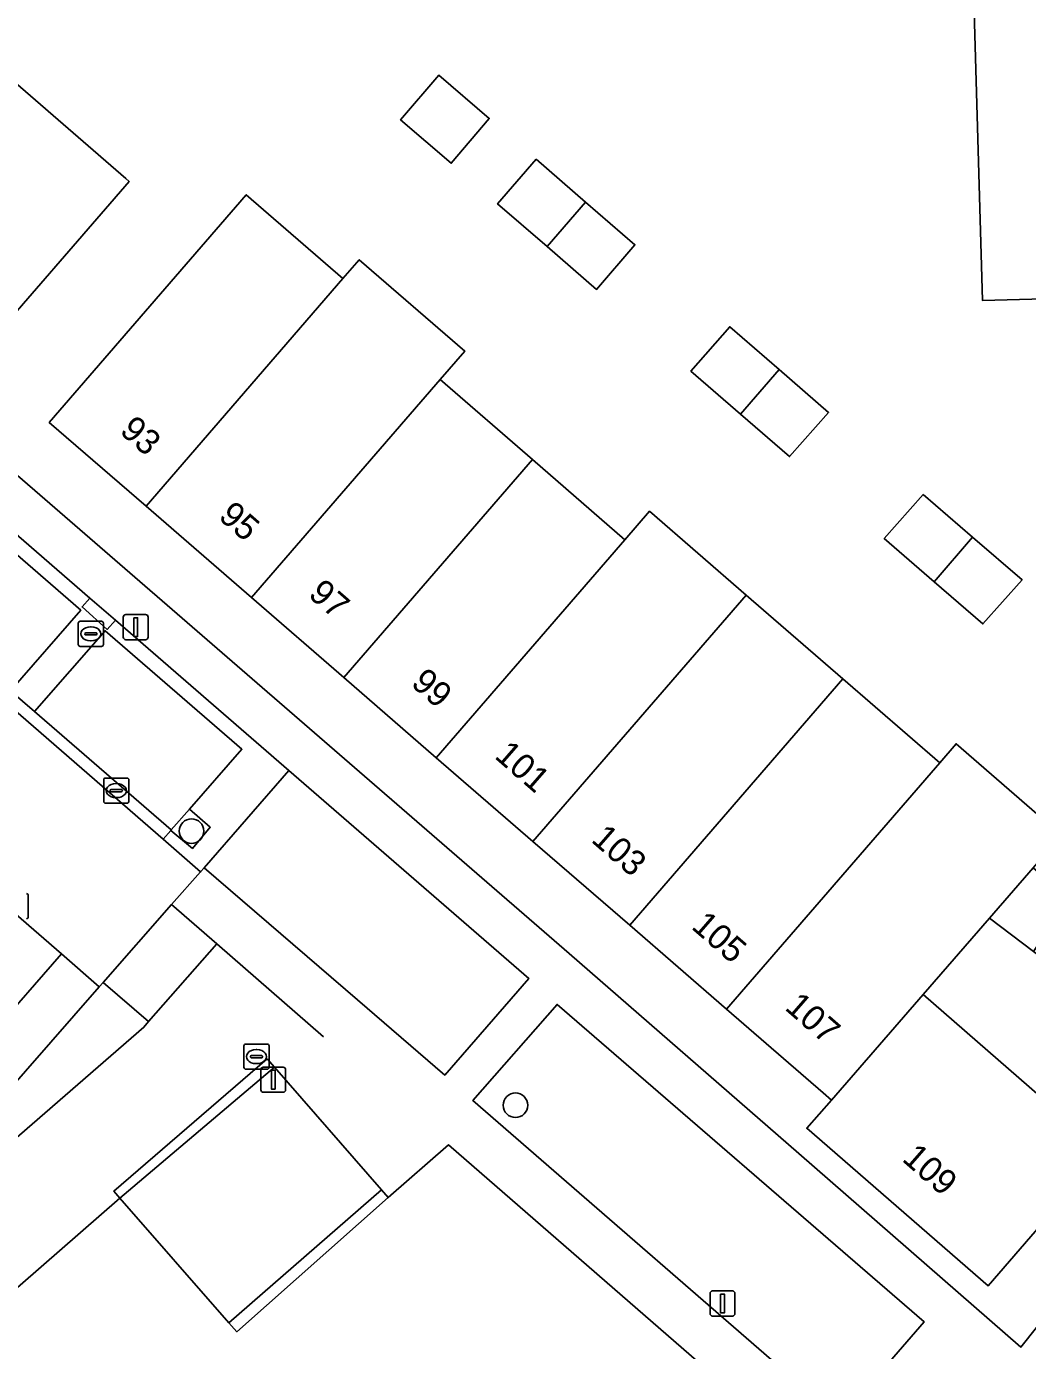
# Model space of a CAD drawing. Extents: x 161881 to 162523, y 381678 to 382381.
# Drawn here: x 162037.1 to 162077, y 382137.3 to 382190.1 of the extents above; entities that cross this region are included whole.
import ezdxf

# ---------------------------------------------------------------- set-up
doc = ezdxf.new("R2010")
doc.units = 0
for name, color, linetype in [('IMGEO_Boom', 7, 'Continuous'), ('IMGEO_Erf', 7, 'Continuous'), ('IMGEO_Groenvoorziening', 7, 'Continuous'), ('IMGEO_Kolk', 7, 'Continuous'), ('IMGEO_Lichtmast', 7, 'Continuous'), ('IMGEO_Muur', 7, 'Continuous'), ('IMGEO_Pand', 7, 'Continuous'), ('IMGEO_Pand_nummerreeks', 7, 'Continuous'), ('IMGEO_Parkeervlak_open', 7, 'Continuous'), ('IMGEO_Rijbaan_lokaal_open', 7, 'Continuous'), ('IMGEO_Rioolput', 7, 'Continuous'), ('IMGEO_Voetpad_op_trap', 7, 'Continuous'), ('IMGEO_Voetpad_open', 7, 'Continuous')]:
    doc.layers.add(name, color=color, linetype=linetype)

msp = doc.modelspace()

# ---------------------------------------------------------------- linework, layer by layer
at = {"layer": 'IMGEO_Boom'}
for centre in [(162043.641, 382158.015), (162056.555, 382147.095)]:
    msp.add_circle(centre, 0.489, dxfattribs=at)
at = {"layer": 'IMGEO_Erf'}
for points in [[(162018.121, 382203.859), (162041.023, 382184.008), (162041.152, 382183.891), (162035.04, 382176.852)], [(162081.552, 382179.326), (162075.168, 382179.155), (162074.741, 382193.897)], [(162078.978, 382144.027), (162075.391, 382139.899), (162068.168, 382146.176), (162069.146, 382147.302), (162068.814, 382147.589), (162064.963, 382150.924), (162061.108, 382154.263), (162057.252, 382157.602), (162053.397, 382160.94), (162049.714, 382164.13), (162046.032, 382167.319), (162041.828, 382170.959), (162037.971, 382174.299), (162045.823, 382183.364), (162049.678, 382180.025), (162050.33, 382180.778), (162054.534, 382177.137), (162053.552, 382176.003), (162057.235, 382172.814), (162060.917, 382169.624), (162061.899, 382170.758), (162065.755, 382167.418), (162069.61, 382164.079), (162073.466, 382160.739), (162074.121, 382161.495), (162077.841, 382158.272)], [(162034.901, 382173.742), (162058.69, 382153.142), (162067.845, 382145.177), (162076.705, 382137.459), (162080.965, 382142.814)]]:
    msp.add_lwpolyline(points, dxfattribs=at)
for points in [[(162055.51, 382186.41), (162053.994, 382184.622), (162051.976, 382186.353), (162053.505, 382188.131)], [(162057.377, 382184.78), (162059.348, 382183.077), (162061.318, 382181.373), (162059.787, 382179.597), (162057.814, 382181.302), (162055.845, 382183.003)], [(162067.068, 382176.399), (162069.039, 382174.69), (162067.483, 382172.937), (162065.531, 382174.627), (162063.551, 382176.342), (162065.097, 382178.108)], [(162072.803, 382171.429), (162074.775, 382169.729), (162076.747, 382168.029), (162075.189, 382166.27), (162073.242, 382167.951), (162071.254, 382169.668)], [(162077.199, 382153.219), (162075.448, 382154.554), (162072.802, 382151.509), (162080.025, 382145.232), (162078.978, 382144.027), (162079.761, 382143.345), (162080.668, 382142.557), (162080.678, 382142.57), (162080.908, 382142.859), (162082.372, 382144.704), (162084.632, 382147.554), (162084.682, 382147.616), (162084.141, 382148.045), (162084.083, 382147.972)]]:
    msp.add_lwpolyline(points, close=True, dxfattribs=at)
at = {"layer": 'IMGEO_Groenvoorziening'}
for points in [[(162047.527, 382160.427), (162044.151, 382156.557), (162050.254, 382151.288), (162053.738, 382148.295), (162057.087, 382152.15)], [(162043.557, 382158.895), (162042.829, 382158.065), (162042.811, 382158.044), (162043.675, 382157.326), (162044.388, 382158.167)], [(162041.933, 382150.436), (162040.113, 382151.987), (162039.963, 382151.816), (162031.132, 382141.739), (162031.515, 382141.331), (162041.747, 382150.205)], [(162058.213, 382151.114), (162054.859, 382147.282), (162069.486, 382134.586), (162072.851, 382138.463)], [(162051.211, 382143.73), (162046.944, 382148.616), (162040.79, 382143.399), (162045.133, 382138.43)], [(162065.711, 382135.244), (162053.879, 382145.512), (162051.478, 382143.425), (162045.443, 382138.075), (162045.133, 382138.43), (162040.79, 382143.399), (162034.496, 382137.927), (162055.435, 382113.796), (162063.942, 382121.182), (162066.058, 382123), (162059.846, 382130.148)]]:
    msp.add_lwpolyline(points, close=True, dxfattribs=at)
at = {"layer": 'IMGEO_Kolk'}
for p, q in [((162040.142, 382159.202), (162040.142, 382160.054)), ((162040.217, 382160.128), (162041.069, 382160.128)), ((162040.444, 382159.671), (162040.842, 382159.671)), ((162040.63, 382159.908), (162040.655, 382159.908)), ((162041.143, 382160.054), (162041.143, 382159.202)), ((162041.069, 382159.128), (162040.217, 382159.128)), ((162040.401, 382159.622), (162040.401, 382159.634)), ((162040.839, 382159.585), (162040.441, 382159.585)), ((162040.653, 382159.348), (162040.628, 382159.348)), ((162040.885, 382159.634), (162040.885, 382159.622)), ((162037.136, 382155.45), (162037.136, 382154.598)), ((162045.731, 382148.606), (162045.731, 382149.458)), ((162045.806, 382149.532), (162046.658, 382149.532)), ((162046.219, 382149.312), (162046.244, 382149.312)), ((162046.732, 382149.458), (162046.732, 382148.606)), ((162045.99, 382149.026), (162045.99, 382149.038)), ((162046.428, 382148.989), (162046.03, 382148.989)), ((162046.033, 382149.075), (162046.431, 382149.075)), ((162046.242, 382148.752), (162046.217, 382148.752)), ((162046.474, 382149.038), (162046.474, 382149.026)), ((162046.658, 382148.532), (162045.806, 382148.532))]:
    msp.add_line(p, q, dxfattribs=at)
for points in [[(162040.142, 382159.202), (162040.142, 382160.054)], [(162040.217, 382160.128), (162041.069, 382160.128)], [(162041.143, 382160.054), (162041.143, 382159.202)], [(162041.069, 382159.128), (162040.217, 382159.128)], [(162037.136, 382155.45), (162037.136, 382154.598)], [(162045.731, 382148.606), (162045.731, 382149.458)], [(162045.806, 382149.532), (162046.658, 382149.532)], [(162046.732, 382149.458), (162046.732, 382148.606)], [(162046.658, 382148.532), (162045.806, 382148.532)]]:
    msp.add_lwpolyline(points, dxfattribs=at)
for centre, radius, start, end in [((162040.219, 382160.052), 0.0765, 91.552, 178.448), ((162040.219, 382160.052), 0.0765, 91.552, 178.448), ((162040.441, 382159.631), 0.0403, 85.8775, 175.7526), ((162040.846, 382159.633), 0.0386, 1.7309, 96.639), ((162041.067, 382160.052), 0.0765, 1.552, 88.448), ((162041.067, 382160.052), 0.0765, 1.552, 88.448), ((162040.219, 382159.204), 0.0765, 181.552, 268.448), ((162040.219, 382159.204), 0.0765, 181.552, 268.448), ((162040.438, 382159.621), 0.0366, 178.938, 274.7102), ((162040.842, 382159.628), 0.043, 264.8664, 352.4533), ((162041.067, 382159.204), 0.0765, 271.552, 358.448), ((162041.067, 382159.204), 0.0765, 271.552, 358.448), ((162037.06, 382155.448), 0.0765, 1.552, 88.448), ((162037.06, 382155.448), 0.0765, 1.552, 88.448), ((162037.06, 382154.6), 0.0765, 271.552, 358.448), ((162037.06, 382154.6), 0.0765, 271.552, 358.448), ((162045.808, 382149.456), 0.0765, 91.552, 178.448), ((162045.808, 382149.456), 0.0765, 91.552, 178.448), ((162046.656, 382149.456), 0.0765, 1.552, 88.448), ((162046.656, 382149.456), 0.0765, 1.552, 88.448), ((162045.808, 382148.608), 0.0765, 181.552, 268.448), ((162045.808, 382148.608), 0.0765, 181.552, 268.448), ((162046.03, 382149.035), 0.0403, 85.8775, 175.7526), ((162046.027, 382149.025), 0.0366, 178.938, 274.7102), ((162046.431, 382149.032), 0.043, 264.8664, 352.4533), ((162046.435, 382149.037), 0.0386, 1.7309, 96.639), ((162046.656, 382148.608), 0.0765, 271.552, 358.448), ((162046.656, 382148.608), 0.0765, 271.552, 358.448)]:
    msp.add_arc(centre, radius, start, end, dxfattribs=at)
for centre, major_axis, ratio, start_param, end_param in [((162040.629, 382159.628), (-0.387, 0.002), 0.722429, 4.712389, 7.853982), ((162040.654, 382159.628), (-0.39, 0.002), 0.717154, 1.570796, 4.712389), ((162046.218, 382149.032), (-0.387, 0.002), 0.722429, 4.712389, 7.853982), ((162046.243, 382149.032), (-0.39, 0.002), 0.717154, 1.570796, 4.712389)]:
    msp.add_ellipse(centre, major_axis=major_axis, ratio=ratio, start_param=start_param, end_param=end_param, dxfattribs=at)
at = {"layer": 'IMGEO_Lichtmast'}
for p, q in [((162040.922, 382165.741), (162040.922, 382166.541)), ((162040.922, 382166.541), (162040.922, 382165.741)), ((162041.022, 382166.641), (162041.812, 382166.641)), ((162041.812, 382166.641), (162041.022, 382166.641)), ((162041.912, 382166.541), (162041.912, 382165.741)), ((162041.912, 382165.741), (162041.912, 382166.541)), ((162041.812, 382165.641), (162041.022, 382165.641)), ((162041.022, 382165.641), (162041.812, 382165.641)), ((162046.504, 382148.611), (162047.294, 382148.611)), ((162047.294, 382148.611), (162046.504, 382148.611)), ((162046.404, 382147.711), (162046.404, 382148.511)), ((162046.404, 382148.511), (162046.404, 382147.711)), ((162047.394, 382148.511), (162047.394, 382147.711)), ((162047.394, 382147.711), (162047.394, 382148.511)), ((162047.294, 382147.611), (162046.504, 382147.611)), ((162046.504, 382147.611), (162047.294, 382147.611)), ((162064.414, 382139.697), (162065.204, 382139.697)), ((162065.204, 382139.697), (162064.414, 382139.697)), ((162064.314, 382138.797), (162064.314, 382139.597)), ((162064.314, 382139.597), (162064.314, 382138.797)), ((162065.304, 382139.597), (162065.304, 382138.797)), ((162065.304, 382138.797), (162065.304, 382139.597)), ((162065.204, 382138.697), (162064.414, 382138.697)), ((162064.414, 382138.697), (162065.204, 382138.697))]:
    msp.add_line(p, q, dxfattribs=at)
for points in [[(162041.342, 382166.516), (162041.492, 382166.516), (162041.492, 382165.766), (162041.342, 382165.766), (162041.342, 382166.516)], [(162046.824, 382148.486), (162046.974, 382148.486), (162046.974, 382147.736), (162046.824, 382147.736), (162046.824, 382148.486)], [(162064.734, 382139.572), (162064.884, 382139.572), (162064.884, 382138.822), (162064.734, 382138.822), (162064.734, 382139.572)]]:
    msp.add_lwpolyline(points, dxfattribs=at)
for centre, start, end in [((162041.022, 382166.541), 90, 180), ((162041.022, 382166.541), 90, 180), ((162041.812, 382166.541), 0, 90), ((162041.812, 382166.541), 360, 90), ((162041.022, 382165.741), 180, 270), ((162041.022, 382165.741), 180, 270), ((162041.812, 382165.741), 270, 0), ((162041.812, 382165.741), 270, 0), ((162046.504, 382148.511), 90, 180), ((162046.504, 382148.511), 90, 180), ((162047.294, 382148.511), 0, 90), ((162047.294, 382148.511), 360, 90), ((162046.504, 382147.711), 180, 270), ((162046.504, 382147.711), 180, 270), ((162047.294, 382147.711), 270, 0), ((162047.294, 382147.711), 270, 0), ((162064.414, 382139.597), 90, 180), ((162064.414, 382139.597), 90, 180), ((162065.204, 382139.597), 0, 90), ((162065.204, 382139.597), 360, 90), ((162064.414, 382138.797), 180, 270), ((162064.414, 382138.797), 180, 270), ((162065.204, 382138.797), 270, 0), ((162065.204, 382138.797), 270, 0)]:
    msp.add_arc(centre, 0.1, start, end, dxfattribs=at)
at = {"layer": 'IMGEO_Muur'}
msp.add_lwpolyline([(162048.896, 382149.822), (162044.647, 382153.525)], dxfattribs=at)
for points in [[(162046.944, 382148.616), (162046.652, 382148.942), (162040.548, 382143.677), (162040.79, 382143.399)], [(162051.478, 382143.425), (162051.211, 382143.73), (162045.133, 382138.43), (162045.443, 382138.075)]]:
    msp.add_lwpolyline(points, close=True, dxfattribs=at)
at = {"layer": 'IMGEO_Pand'}
for points in [[(162018.121, 382203.859), (162014.282, 382207.186), (162010.443, 382210.514), (162004.335, 382203.455), (162035.04, 382176.852), (162041.152, 382183.891), (162041.023, 382184.008)], [(162053.994, 382184.622), (162055.51, 382186.41), (162053.505, 382188.131), (162051.976, 382186.353)], [(162057.377, 382184.78), (162055.845, 382183.003), (162057.814, 382181.302), (162059.348, 382183.077)], [(162049.678, 382180.025), (162045.823, 382183.364), (162037.971, 382174.299), (162041.828, 382170.959)], [(162059.348, 382183.077), (162057.814, 382181.302), (162059.787, 382179.597), (162061.318, 382181.373)], [(162053.552, 382176.003), (162054.534, 382177.137), (162050.33, 382180.778), (162049.678, 382180.025), (162041.828, 382170.959), (162046.032, 382167.319)], [(162067.068, 382176.399), (162065.097, 382178.108), (162063.551, 382176.342), (162065.531, 382174.627)], [(162069.039, 382174.69), (162067.068, 382176.399), (162065.531, 382174.627), (162067.483, 382172.937)], [(162057.235, 382172.814), (162053.552, 382176.003), (162046.032, 382167.319), (162049.714, 382164.13)], [(162060.917, 382169.624), (162057.235, 382172.814), (162049.714, 382164.13), (162053.397, 382160.94)], [(162072.803, 382171.429), (162071.254, 382169.668), (162073.242, 382167.951), (162074.775, 382169.729)], [(162065.755, 382167.418), (162061.899, 382170.758), (162060.917, 382169.624), (162053.397, 382160.94), (162057.252, 382157.602)], [(162076.747, 382168.029), (162074.775, 382169.729), (162073.242, 382167.951), (162075.189, 382166.27)], [(162069.61, 382164.079), (162065.755, 382167.418), (162057.252, 382157.602), (162061.108, 382154.263)], [(162073.466, 382160.739), (162069.61, 382164.079), (162061.108, 382154.263), (162064.963, 382150.924)], [(162075.448, 382154.554), (162077.186, 382156.555), (162078.318, 382157.859), (162077.841, 382158.272), (162074.121, 382161.495), (162073.466, 382160.739), (162064.963, 382150.924), (162068.814, 382147.589), (162069.146, 382147.302), (162072.802, 382151.509)], [(162078.615, 382155.313), (162077.186, 382156.555), (162075.448, 382154.554), (162077.199, 382153.219)], [(162072.802, 382151.509), (162069.146, 382147.302), (162068.168, 382146.176), (162075.391, 382139.899), (162078.978, 382144.027), (162080.025, 382145.232)]]:
    msp.add_lwpolyline(points, close=True, dxfattribs=at)
msp.add_lwpolyline([(162067.56, 382193.772), (162067.774, 382193.996), (162067.692, 382194.083), (162071.649, 382198.284), (162073.593, 382196.41), (162078.546, 382196.531), (162078.626, 382194.019), (162074.741, 382193.897), (162075.168, 382179.155), (162081.552, 382179.326), (162084.022, 382177.24), (162082.333, 382175.326), (162082.586, 382175.12), (162085.015, 382177.926), (162087.132, 382180.372), (162087.289, 382180.239), (162092.935, 382186.87), (162092.832, 382186.958), (162085.181, 382194.323)], dxfattribs=at)
at = {"layer": 'IMGEO_Parkeervlak_open'}
for points in [[(162033.785, 382171.53), (162031.705, 382169.163), (162030.974, 382168.332), (162036.426, 382163.61), (162039.223, 382166.817)], [(162037.387, 382162.778), (162042.829, 382158.065), (162043.557, 382158.895), (162045.649, 382161.279), (162040.199, 382165.998)], [(162036.646, 382154.691), (162033.054, 382157.803), (162030.242, 382154.62), (162035.668, 382149.938), (162038.456, 382153.122)]]:
    msp.add_lwpolyline(points, close=True, dxfattribs=at)
at = {"layer": 'IMGEO_Rijbaan_lokaal_open'}
msp.add_lwpolyline([(162023.729, 382174.608), (162018.255, 382179.355), (162017.419, 382180.08), (162011.989, 382184.789), (162011.011, 382185.637), (162005.61, 382190.321), (162004.744, 382191.044), (162004.578, 382191.195), (162004.274, 382190.846), (162005.488, 382189.784), (162024.055, 382173.714), (162042.512, 382157.689), (162042.811, 382158.044), (162042.829, 382158.065), (162037.387, 382162.778), (162036.426, 382163.61), (162030.974, 382168.332), (162030.15, 382169.045), (162024.683, 382173.78), (162024.348, 382174.07)], close=True, dxfattribs=at)
msp.add_lwpolyline([(162036.646, 382154.691), (162038.456, 382153.122), (162039.963, 382151.816), (162040.113, 382151.987), (162042.849, 382155.091), (162044.005, 382156.393), (162042.512, 382157.689), (162024.055, 382173.714)], dxfattribs=at)
at = {"layer": 'IMGEO_Rioolput'}
for p, q in [((162039.129, 382165.448), (162039.129, 382166.3)), ((162039.204, 382166.374), (162040.056, 382166.374)), ((162039.617, 382166.154), (162039.642, 382166.154)), ((162040.13, 382166.3), (162040.13, 382165.448)), ((162039.388, 382165.868), (162039.388, 382165.88)), ((162039.826, 382165.831), (162039.428, 382165.831)), ((162039.431, 382165.917), (162039.829, 382165.917)), ((162039.64, 382165.594), (162039.615, 382165.594)), ((162039.872, 382165.88), (162039.872, 382165.868)), ((162040.056, 382165.374), (162039.204, 382165.374))]:
    msp.add_line(p, q, dxfattribs=at)
for points in [[(162039.129, 382165.448), (162039.129, 382166.3)], [(162039.204, 382166.374), (162040.056, 382166.374)], [(162040.13, 382166.3), (162040.13, 382165.448)], [(162040.056, 382165.374), (162039.204, 382165.374)]]:
    msp.add_lwpolyline(points, dxfattribs=at)
for centre, radius, start, end in [((162039.206, 382166.298), 0.0765, 91.552, 178.448), ((162039.206, 382166.298), 0.0765, 91.552, 178.448), ((162040.054, 382166.298), 0.0765, 1.552, 88.448), ((162040.054, 382166.298), 0.0765, 1.552, 88.448), ((162039.428, 382165.877), 0.0403, 85.8775, 175.7526), ((162039.425, 382165.867), 0.0366, 178.938, 274.7102), ((162039.829, 382165.874), 0.043, 264.8664, 352.4533), ((162039.833, 382165.879), 0.0386, 1.7309, 96.639), ((162039.206, 382165.45), 0.0765, 181.552, 268.448), ((162039.206, 382165.45), 0.0765, 181.552, 268.448), ((162040.054, 382165.45), 0.0765, 271.552, 358.448), ((162040.054, 382165.45), 0.0765, 271.552, 358.448)]:
    msp.add_arc(centre, radius, start, end, dxfattribs=at)
for centre, major_axis, ratio, start_param, end_param in [((162039.616, 382165.874), (-0.387, 0.002), 0.722429, 4.712389, 7.853982), ((162039.641, 382165.874), (-0.39, 0.002), 0.717154, 1.570796, 4.712389)]:
    msp.add_ellipse(centre, major_axis=major_axis, ratio=ratio, start_param=start_param, end_param=end_param, dxfattribs=at)
at = {"layer": 'IMGEO_Voetpad_op_trap'}
for points in [[(162039.593, 382167.298), (162039.278, 382166.945), (162040.281, 382166.05), (162040.609, 382166.418)], [(162044.647, 382153.525), (162042.849, 382155.091), (162040.113, 382151.987), (162041.933, 382150.436)]]:
    msp.add_lwpolyline(points, close=True, dxfattribs=at)
at = {"layer": 'IMGEO_Voetpad_open'}
for points in [[(162030.56, 382175.118), (162039.593, 382167.298), (162040.609, 382166.418), (162047.527, 382160.427), (162057.087, 382152.15), (162053.738, 382148.295), (162050.254, 382151.288), (162044.151, 382156.557), (162044.005, 382156.393), (162042.849, 382155.091), (162044.647, 382153.525), (162041.933, 382150.436), (162041.747, 382150.205), (162031.515, 382141.331)], [(162033.785, 382171.53), (162039.223, 382166.817), (162036.426, 382163.61), (162037.387, 382162.778), (162040.199, 382165.998), (162045.649, 382161.279), (162043.557, 382158.895), (162044.388, 382158.167), (162043.675, 382157.326), (162042.811, 382158.044), (162042.512, 382157.689), (162044.005, 382156.393), (162044.151, 382156.557), (162047.527, 382160.427), (162040.609, 382166.418), (162040.281, 382166.05), (162039.278, 382166.945), (162039.593, 382167.298), (162030.56, 382175.118)], [(162084.661, 382140.952), (162085.631, 382142.179), (162082.372, 382144.704), (162080.908, 382142.859), (162080.965, 382142.814), (162076.705, 382137.459), (162067.845, 382145.177), (162058.69, 382153.142), (162034.901, 382173.742)], [(162031.132, 382141.739), (162039.963, 382151.816), (162038.456, 382153.122), (162035.668, 382149.938)], [(162034.321, 382102.015), (162049.626, 382115.318), (162049.638, 382115.532), (162050.725, 382116.472), (162054.076, 382112.578), (162055.435, 382113.796), (162034.496, 382137.927), (162040.79, 382143.399), (162040.548, 382143.677), (162046.652, 382148.942)], [(162046.652, 382148.942), (162046.944, 382148.616), (162051.211, 382143.73), (162051.478, 382143.425), (162053.879, 382145.512), (162065.711, 382135.244), (162059.846, 382130.148), (162066.058, 382123), (162077.927, 382133.363), (162078.874, 382134.178), (162079.109, 382134.375)]]:
    msp.add_lwpolyline(points, dxfattribs=at)
msp.add_lwpolyline([(162054.859, 382147.282), (162058.213, 382151.114), (162072.851, 382138.463), (162069.486, 382134.586)], close=True, dxfattribs=at)

# ---------------------------------------------------------------- texts
at = {"layer": 'IMGEO_Pand_nummerreeks'}
for s, rotation, p in [('93', 318.9075, (162040.735, 382173.893)), ('95', 318.9075, (162044.672, 382170.484)), ('97', 318.9075, (162048.253, 382167.383)), ('99', 318.9075, (162052.345, 382163.839)), ('101', 318.9075, (162055.68, 382160.954)), ('103', 318.9075, (162059.531, 382157.62)), ('105', 318.9075, (162063.524, 382154.162)), ('107', 318.9075, (162067.252, 382150.933)), ('109', 318.8101, (162071.923, 382144.905))]:
    msp.add_text(s, height=1, rotation=rotation, dxfattribs=at).set_placement(p)

doc.saveas('drawing.dxf')
